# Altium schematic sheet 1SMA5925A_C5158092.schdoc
size 127 x 101 mm
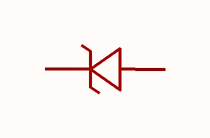
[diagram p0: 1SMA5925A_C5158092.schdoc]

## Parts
D?  1sma5925a_c5158092  [SMA_L4.3-W2.6-LS5.1-RD]  (value not drawn)

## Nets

Not connected (* = marked no-connect by the designer): D? 1(K) 2(A)

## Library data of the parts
D? = 1sma5925a_c5158092: 二极管配置:1个独立式;稳压值(标称值):10V;稳压值(范围值):9.5V~10.5V;耗散功率(Pd):1.5W;; Manufacturer: CJ(江苏长电/长晶); AddInBom: yes; ModelId: 1d20a911e9694ba6aaf6e9207164e4da; ModelTransform: 196.4563,102.362,0,0,0,0,0.001,-0.001,0; Diode Configuration: 1个独立式; Zener Voltage(Nom): 10V; Reverse Leakage Current (Ir): 2.5uA; Pd - Power Dissipation: 1.5W; Impedance(Zzt): 4.5Ω; Impedance(Zzk): 500Ω; Operating Junction Temperature Range: -55℃~+150℃; Tolerance: ±5%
